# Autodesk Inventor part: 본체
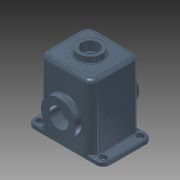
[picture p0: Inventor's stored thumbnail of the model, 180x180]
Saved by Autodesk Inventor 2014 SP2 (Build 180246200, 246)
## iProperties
Company: 한국ATC센터
Created: 2014-10
Part Number: 본체
Document SubType Name: Modeling
Designer: 한국ATC센터
Density: 2.71 g/cm^3
Material: 알루미늄 6061
Mass: 3285.47 g
Surface Area: 2358.49 cm^2
Volume: 1212.35 cm^3
Appearance: 청회색(진함/광택)
Author: KYOUNG IL JANG
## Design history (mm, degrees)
sketch "스케치1"
  geometry: L1 (-70, 65)-(70, 65); L2 (70, 65)-(70, -65); L3 (70, -65)-(-70, -65); L4 (-70, -65)-(-70, 65); 3 further points
  constraints: 8 end point, 2 midpoint, 2 parallel, 1 horizontal, 1 horizontal alignment, 1 perpendicular, 1 vertical alignment
  dimensions: "d0" = 140 distance of L2.end L3.end; "d68" = 130 distance of L3.end L1.start
extrude "돌출1" new body sketch "스케치1" distance "d1" = 180; taper "d2" = 0 deg
fillet "모깎기1" dims "d3" = 20
feature "쉘1" dims "d4" = 10
sketch "스케치2"
  geometry: L1 (-70, 45)-(-70, -45) reference; L2 (-50, -65)-(-82, -65); L3 (-82, 65)-(-50, 65); L4 (-85, 57)-(-82, 57); L5 (-82, 41)-(-85, 41); L6 (-100, 47)-(-100, -47); A1 r 20 centre (-50, 45) between (-50, 65) and (-70, 45) reference; A2 r 20 centre (-50, -45) between (-70, -45) and (-50, -65) reference; A3 r 8 centre (-82, 49) between (-82, 41) and (-82, 57); A4 r 8 centre (-85, 49) between (-85, 57) and (-85, 41); A5 r 18 centre (-82, 47) between (-82, 65) and (-100, 47); A6 r 18 centre (-82, -47) between (-100, -47) and (-82, -65); 1 further point
  constraints: 10 end point, 9 tangent, 8 point on circle, 4 centre point, 2 parallel, 2 perpendicular, 1 equal radius
  dimensions: "d6" = 49 vertical distance of point (0, 0) A3.centre; "d8" = 16 distance between parallel lines of L4 L5; "d64" = 18 radius of A5; "d65" = 12 distance from line of A3.centre L1; "d66" = 30 distance between parallel lines of L6 L1; "d67" = 3 distance of A4.centre A3.centre
extrude "돌출2" join sketch "스케치2" distance "d9" = 10; taper "d10" = 0 deg
extrude "돌출3" cut sketch "스케치2" stored distance "d11" = 10; taper "d12" = 0 deg
sketch "스케치3"
  geometry: L1 (-65, 0)-(-65, 180) reference; L2 (-55, 0)-(-55, 170) reference; L3 (-83, 75)-(-51, 75); L4 (45, 0)-(-45, 0) reference; L5 (-83, 75)-(-83, 120.5); L6 (-83, 120.5)-(-55, 120.5); L7 (-55, 120.5)-(-51, 116.5); L8 (-51, 116.5)-(-51, 75); 2 further points
  constraints: 10 end point, 4 perpendicular, 1 point on line
  dimensions: "d13" = 75 distance between parallel lines of L3 L4; "d14" = 18 distance from line of L1 L3.start; "d15" = 4 distance from line of L3.end L2; "d16" = 91 diameter of L6 L3; "d17" = 135 deg angle of L7 L2
revolve "회전1" sketch "스케치3" stored, may be unused: angle "d18" = 90 deg
sketch "스케치4"
  geometry: C1 r 45.5 at (0, 0) reference; 2 further points
  constraints: 1 vertical alignment
  dimensions: "d19" = 35 distance of C1.centre point (0, 35)
hole "구멍1" sketch "스케치4" at (0, 35) diameter "d20" = 3.459; stored, may be unused: countersink angle "d24" = 90 deg, drill point angle "d26" = 118 deg; dims "d21" = 13, "d22" = 4, "d23" = 2, "d25" = 16
fillet "모깎기2" dims "d30" = 3
hole "구멍2" diameter "d33" = 52; stored, may be unused: countersink angle "d37" = 90 deg, drill point angle "d39" = 118 deg; dims "d31" = 10, "d32" = 10, "d34" = 13, "d35" = 4, "d36" = 2, "d38" = 16
sketch "스케치5"
  geometry: C1 r 31 at (0, 0); 1 further point
  constraints: 1 centre point, 1 coincident
  dimensions: "d40" = 62 diameter of C1
extrude "돌출4" join sketch "스케치5" distance "d41" = 15; taper "d42" = 0 deg
hole "구멍3" diameter "d45" = 43; stored, may be unused: countersink angle "d49" = 90 deg, drill point angle "d51" = 118 deg; dims "d43" = 10, "d44" = 10, "d46" = 13, "d47" = 4, "d48" = 2, "d50" = 16
fillet "모깎기3" dims "d52" = 3
fillet "모깎기4" dims "d53" = 3
chamfer "모따기1" distance "d55" = 1; stored, may be unused: second distance "d56" = 2, angle "d57" = 45 deg
sketch "스케치6"
  geometry: 2 further points
  constraints: 1 vertical alignment, 1 other
  dimensions: "d71" = 90 distance of point (0, 0) point (0, 90)
feature "엠보싱2" sketch "스케치6" dims "d0" = 140, "d68" = 130, "d72" = 1, "d73" = 0
fillet "모깎기6" dims "d74" = 10
sketch "스케치7"
  geometry: C1 r 15 at (0, 0); C2 r 21.5 at (0, 0) reference; C3 r 25 at (0, 0); 1 further point
  constraints: 2 centre point, 2 coincident
  dimensions: "d61" = 30 diameter of C1; "d75" = 50 diameter of C3
extrude "돌출5" join sketch "스케치7" distance "d62" = 10; taper "d63" = 0 deg
feature "면 이동1" dims "d76" = 1
fillet "모깎기7" dims "d77" = 3
node "솔리드1"
mirror "대칭1"
mirror "대칭2"
pattern_circular "원형 패턴1" dims angle "d28" = 360 deg
mirror "대칭3"
